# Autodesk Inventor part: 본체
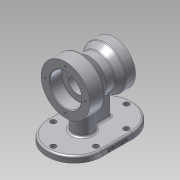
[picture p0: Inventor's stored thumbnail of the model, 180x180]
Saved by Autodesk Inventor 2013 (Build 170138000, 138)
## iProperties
Created: 2020-01
Part Number: 본체
Material: 알루미늄 6061
Document SubType Name: Modeling
Designer: Administrator
Density: 2.71 g/cm^3
Mass: 941.582 g
Surface Area: 654.888 cm^2
Volume: 347.447 cm^3
Author: Administrator
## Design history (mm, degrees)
sketch "스케치1"
  geometry: L1 (-40, 0)-(40, 0); L2 (-40, 0)-(-40, 26); L3 (-40, 40)-(-16, 40); L4 (-16, 40)-(-1.103, 27.5); L5 (-1.103, 27.5)-(13.289, 27.5); L6 (13.289, 27.5)-(24, 35); L7 (24, 35)-(40, 35); L8 (40, 35)-(40, 20); L9 (-40, 26)-(-20, 26); L10 (-20, 26)-(-20, 16); L11 (-20, 16)-(23, 16); L12 (23, 16)-(23, 20); L13 (23, 20)-(40, 20); L14 (-40, 26)-(-40, 40); L15 (40, 20)-(40, 0); 1 further point
  constraints: 30 end point, 9 perpendicular, 8 parallel, 1 horizontal, 1 midpoint
  dimensions: "d0" = 80 distance of L1.start L1.end; "d2" = 24 distance of L3.start L3.end; "d4" = 40 deg angle of L5 L4; "d5" = 35 deg angle of L5 L6; "d6" = 20 distance of L2.end L9.end; "d7" = 17 distance of L12.end L8.end; "d8" = 80 diameter of L3 L1; "d9" = 55 diameter of L5 L1; "d10" = 52 diameter of L9 L1; "d11" = 40 diameter of L13 L1; "d12" = 32 diameter of L11 L1; "d13" = 16 distance from line of L6.end L8; "d14" = 70 diameter of L7 L1; "d15" = 40 distance from line of point (0, 0) L2
revolve "회전1" sketch "스케치1" stored, may be unused: angle "d16" = 90 deg
sketch "스케치2"
  geometry: 1 further point
node "작업 평면1"
sketch "스케치3"
  geometry: L1 (25, 45)-(-25, 45); L2 (25, -45)-(-25, -45); A1 r 45 centre (25, 0) between (25, 45) and (25, -45); A2 r 45 centre (-25, 0) between (-25, 45) and (-25, -45); 2 further points
  constraints: 4 end point, 4 point on circle, 4 tangent, 2 centre point, 2 horizontal alignment, 1 equal radius, 1 midpoint, 1 vertical alignment
  dimensions: "d18" = 45 radius of A1; "d20" = 50 distance of A2.centre A1.centre
extrude "돌출1" join sketch "스케치3" distance "d21" = 10; taper "d22" = 0 deg
sketch "스케치6"
  geometry: L1 (-12, 5)-(30, 5); L2 (30, 5)-(30, -5); L3 (30, -5)-(-12, -5); L4 (-12, -5)-(-12, 5); L5 (40, -35)-(40, 35) reference; C1 r 16 at (-12, 0); A1 r 45 centre (-25, 0) between (-25, 45) and (-25, -45) reference; 2 further points
  constraints: 8 end point, 2 coincident, 2 parallel, 1 centre point, 1 horizontal, 1 horizontal alignment, 1 midpoint, 1 perpendicular
  dimensions: "d30" = 16 radius of C1; "d31" = 10 distance of L1.end L2.end; "d78" = 10 distance between parallel lines of L2 L5; "d79" = 58 dimension on A1 L4
extrude "돌출2" join sketch "스케치6" stored distance "d33" = 10; taper "d34" = 0 deg
sketch "스케치7"
  geometry: L1 (25, 45)-(-25, 45) reference; L2 (-25, -45)-(25, -45) reference; L3 (25, -35)-(-25, -35); L4 (-25, 35)-(25, 35); C1 r 4.5 at (-60, 0); A1 r 45 centre (25, 0) between (25, -45) and (25, 45) reference; A2 r 45 centre (-25, 0) between (-25, 45) and (-25, -45) reference; A3 r 35 centre (25, 0) between (25, -35) and (25, 35); A4 r 35 centre (-25, 0) between (-25, 35) and (-25, -35); 1 further point
  constraints: 5 point on circle, 4 end point, 3 centre point, 3 other
  dimensions: "d35" = 10 distance between parallel lines of L4 L1; "d36" = 9 diameter of C1
extrude "돌출3" cut sketch "스케치7" stored distance "d37" = 10; taper "d38" = 0 deg
sketch "스케치9"
  geometry: L1 (25, 45)-(-25, 45) reference; L2 (-25, -45)-(25, -45) reference; L3 (-25, 35)-(25, 35); L4 (25, -35)-(-25, -35); C1 r 4.5 at (-25, 35); C2 r 4.5 at (25, 35); C3 r 4.5 at (60, 0); C4 r 4.5 at (25, -35); C5 r 4.5 at (-25, -35); A1 r 45 centre (25, 0) between (25, -45) and (25, 45) reference; A2 r 45 centre (-25, 0) between (-25, 45) and (-25, -45) reference; A3 r 35 centre (25, 0) between (25, -35) and (25, 35); A4 r 35 centre (-25, 0) between (-25, 35) and (-25, -35); 1 further point
  constraints: 7 centre point, 5 point on circle, 4 coincident, 4 end point, 4 equal radius, 3 other
  dimensions: "d39" = 10 distance between parallel lines of L3 L1; "d40" = 9 diameter of C1
extrude "돌출4" cut sketch "스케치9" stored distance "d41" = 10; taper "d42" = 0 deg
sketch "스케치12"
  geometry: C1 r 20 at (0, 0) reference; 1 further point
  constraints: 1 vertical alignment
  dimensions: "d45" = 27.5 distance of C1.centre point (0, 27.5)
hole "구멍1" sketch "스케치12" at (0, 27.5) diameter "d46" = 3.242; stored, may be unused: countersink angle "d50" = 82 deg, drill point angle "d52" = 118 deg; dims "d47" = 9, "d48" = 3.023, "d49" = 2, "d51" = 11
sketch "스케치13"
  geometry: C1 r 40 at (0, 0) reference; 1 further point
  constraints: 1 vertical alignment
  dimensions: "d56" = 33 distance of C1.centre point (0, 33)
hole "구멍2" sketch "스케치13" at (0, 33) diameter "d57" = 3.242; stored, may be unused: countersink angle "d61" = 82 deg, drill point angle "d63" = 118 deg; dims "d58" = 9, "d59" = 3.023, "d60" = 2, "d62" = 11
fillet "모깎기1" dims "d67" = 0.3
chamfer "모따기1" distance "d68" = 1; stored, may be unused: second distance "d69" = 2, angle "d70" = 45 deg
fillet "모깎기2" dims "d71" = 3
fillet "모깎기3" dims "d72" = 3
fillet "모깎기4" dims "d73" = 3
sketch "스케치14"
  geometry: L1 (0, 0)-(50, 0) reference; L2 (-45, 0)-(-45, 7) reference; 2 further points
  constraints: 1 other
  dimensions: "d74" = 70 distance from line of L2 point (25, 4); "d75" = 4 distance from line of L1 point (25, 4)
feature "엠보싱1" sketch "스케치14" dims "d0" = 80, "d2" = 24, "d4" = 40 deg, "d5" = 35 deg, "d6" = 20, "d7" = 17, "d8" = 80, "d9" = 55, "d10" = 52, "d11" = 40, "d12" = 32, "d13" = 16, "d14" = 70, "d15" = 40, "d18" = 45, "d20" = 50, "d76" = 0.5, "d77" = 0
node "솔리드1"
pattern_circular "원형 패턴1" dims angle "d54" = 360 deg
pattern_circular "원형 패턴2" dims angle "d65" = 360 deg
